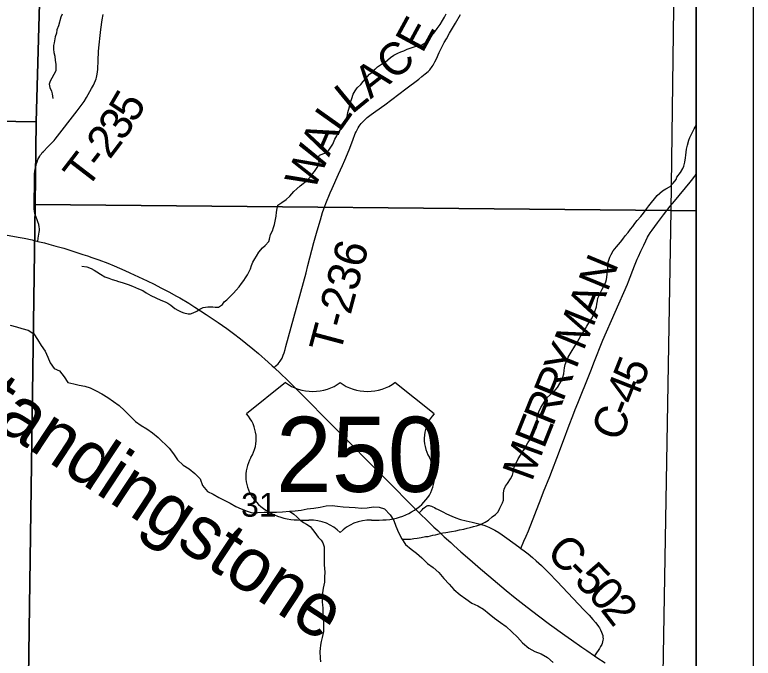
# Model space of a CAD drawing. Extents: x 0 to 34, y 0 to 22.
# Drawn here: x 24.203 to 25.5, y 14.665 to 15.795 of the extents above; entities that cross this region are included whole.
import ezdxf

# ---------------------------------------------------------------- set-up
doc = ezdxf.new("R2010")
doc.units = 0
for name, color, linetype in [('GM_X_Corporation', 7, 'Continuous'), ('GM_X_County_Road', 7, 'Continuous'), ('GM_X_County_Road_Text', 7, 'Continuous'), ('GM_X_Major_River', 7, 'Continuous'), ('GM_X_Major_River_Text', 7, 'Continuous'), ('GM_X_Minor_River', 7, 'Continuous'), ('GM_X_Section_Text', 7, 'Continuous'), ('GM_X_Township_Road', 7, 'Continuous'), ('GM_X_Township_Road_Text', 7, 'Continuous'), ('GM_X_US_Location', 7, 'Continuous'), ('GM_X_US_Route', 7, 'Continuous'), ('GM_X_US_Shield', 7, 'Continuous'), ('SH_Data', 7, 'Continuous')]:
    doc.layers.add(name, color=color, linetype=linetype)

msp = doc.modelspace()

# ---------------------------------------------------------------- linework, layer by layer
at = {"layer": 'GM_X_Corporation'}
msp.add_lwpolyline([(20.2208, 16.9558), (20.1987, 15.2691), (20.203, 14.81), (20.2016, 14.6512), (20.2571, 14.6508), (21.1282, 14.6279), (21.314, 14.623), (22.3464, 14.612), (22.9003, 14.6033), (24.2301, 14.5912), (24.2265, 14.4444), (24.4406, 14.442), (25.338, 14.4317), (25.4, 14.4307), (25.4, 19.0068)], dxfattribs=at)
for points in [[(23.2579, 16.628), (23.7676, 16.6453), (24.2698, 16.6327), (24.2658, 16.4792), (24.2407, 15.6067), (23.2418, 15.623)], [(24.2658, 16.4792), (25.3688, 16.474), (25.3552, 15.4512), (24.2392, 15.4615), (24.2407, 15.6067)], [(25.4, 15.4506), (25.4, 16.4736), (25.3688, 16.474), (25.3552, 15.4512)], [(23.2418, 15.623), (24.2407, 15.6067), (24.2392, 15.4615), (24.2269, 14.5903), (23.2254, 14.5998)], [(24.2392, 15.4615), (25.3552, 15.4512), (25.338, 14.4337), (25.2167, 14.4344), (24.2243, 14.4432), (24.2269, 14.5903)], [(25.4, 14.4329), (25.4, 15.4506), (25.3552, 15.4512), (25.338, 14.4337)]]:
    msp.add_lwpolyline(points, close=True, dxfattribs=at)
at = {"layer": 'GM_X_County_Road'}
for points in [[(25.0917, 14.8577), (25.0975, 14.8702), (25.1016, 14.8794), (25.1053, 14.8884), (25.1275, 14.9457), (25.132, 14.9569), (25.143, 14.984), (25.1478, 14.9961), (25.1553, 15.016), (25.1667, 15.0474), (25.177, 15.0744), (25.1833, 15.0908), (25.1876, 15.1016), (25.1921, 15.1125), (25.2127, 15.1635), (25.215, 15.1696), (25.2212, 15.1867), (25.2257, 15.1982), (25.23, 15.2088), (25.2362, 15.2234), (25.279, 15.3218), (25.2808, 15.3262), (25.2918, 15.3538), (25.2965, 15.3656), (25.2985, 15.3701), (25.3028, 15.3794), (25.3077, 15.3903), (25.3114, 15.3979), (25.3145, 15.404), (25.3161, 15.4069), (25.3193, 15.412), (25.3224, 15.4166), (25.3319, 15.4296), (25.3427, 15.4437), (25.3542, 15.4585), (25.3616, 15.4676), (25.3895, 15.5008), (25.3917, 15.5038), (25.3972, 15.5115), (25.4, 15.5159)], [(24.9136, 14.92), (24.916, 14.9227), (24.9185, 14.9255), (24.9207, 14.9277), (24.9226, 14.9294), (24.9244, 14.9309), (24.9254, 14.9316), (24.9269, 14.9324), (24.9286, 14.9329), (24.9309, 14.933), (24.9326, 14.9326), (24.9351, 14.9317), (24.9373, 14.9307), (24.9401, 14.9293), (24.9429, 14.9278), (24.9467, 14.9259)], [(24.9467, 14.9259), (24.955, 14.9217), (24.9615, 14.9185), (24.9709, 14.9141), (24.975, 14.9124), (24.9794, 14.9106), (24.9824, 14.9095), (24.9858, 14.9085), (24.9962, 14.906), (25.0063, 14.9039), (25.0134, 14.9023), (25.0204, 14.9004), (25.0268, 14.8984), (25.0318, 14.8966), (25.0368, 14.8946), (25.0418, 14.8922), (25.0463, 14.8897), (25.0533, 14.8854), (25.0591, 14.8815), (25.0673, 14.8757), (25.0882, 14.8604), (25.0917, 14.8577), (25.0978, 14.8533), (25.1046, 14.848), (25.1127, 14.8418), (25.119, 14.8362), (25.1281, 14.8278), (25.1361, 14.8199), (25.1409, 14.8151), (25.1558, 14.7996), (25.2026, 14.7501), (25.212, 14.7404), (25.2186, 14.7327), (25.2232, 14.7274), (25.2271, 14.7222), (25.2281, 14.7208)], [(25.2281, 14.7208), (25.23, 14.718), (25.2318, 14.7148), (25.2338, 14.7108), (25.235, 14.7076), (25.2358, 14.7046), (25.2362, 14.7018), (25.2363, 14.699), (25.2361, 14.6967), (25.2356, 14.6939), (25.2348, 14.691), (25.2339, 14.6888), (25.2321, 14.6854), (25.2302, 14.6821), (25.2278, 14.6785), (25.2249, 14.6745), (25.2211, 14.6691)]]:
    msp.add_lwpolyline(points, dxfattribs=at)
at = {"layer": 'GM_X_Major_River'}
for points in [[(24.1955, 15.2495), (24.2062, 15.2466), (24.2161, 15.244), (24.2267, 15.241), (24.237, 15.2347), (24.2431, 15.2245), (24.25, 15.2139), (24.2566, 15.2041), (24.2612, 15.1935), (24.2654, 15.1836), (24.2727, 15.1738), (24.2822, 15.1697), (24.2903, 15.1592), (24.2968, 15.149), (24.3071, 15.1468), (24.3166, 15.1446), (24.3264, 15.1428), (24.3359, 15.1394), (24.3466, 15.1346), (24.3565, 15.1294), (24.3668, 15.1226), (24.3767, 15.1159), (24.3866, 15.1087), (24.3961, 15.1001), (24.4053, 15.0903), (24.4156, 15.0805), (24.4255, 15.0734), (24.4351, 15.0678), (24.4454, 15.0606), (24.4553, 15.0527), (24.4748, 15.0335), (24.4824, 15.0237), (24.4889, 15.0135), (24.4993, 15.0038), (24.5099, 14.9974), (24.5195, 14.9895), (24.529, 14.9801), (24.5333, 14.968), (24.5421, 14.9578), (24.552, 14.9529), (24.5619, 14.947), (24.5722, 14.9417), (24.5817, 14.9369), (24.5916, 14.9316), (24.6011, 14.9272), (24.6112, 14.9229)], [(24.6112, 14.9229), (24.6205, 14.9201), (24.6303, 14.9206), (24.6413, 14.9214), (24.6527, 14.9215), (24.6629, 14.9212), (24.6735, 14.9217), (24.6857, 14.9233), (24.6955, 14.9238), (24.7061, 14.9247), (24.7167, 14.927)], [(24.7167, 14.927), (24.7288, 14.9286), (24.7398, 14.9299), (24.7504, 14.9322), (24.7606, 14.9331), (24.7701, 14.932), (24.7803, 14.931), (24.7906, 14.9303), (24.8012, 14.9293), (24.8122, 14.9286), (24.8224, 14.9291), (24.833, 14.9307), (24.8433, 14.93), (24.8528, 14.9274), (24.8627, 14.9169), (24.8689, 14.9067), (24.8727, 14.8965), (24.8774, 14.8855), (24.8828, 14.8745), (24.8897, 14.8647), (24.8992, 14.8565), (24.9088, 14.8493), (24.9183, 14.8411), (24.9282, 14.8313), (24.9382, 14.8241), (24.9477, 14.8155), (24.9565, 14.8049), (24.9661, 14.7952), (24.9745, 14.7854), (24.9852, 14.776), (24.9955, 14.7692), (25.0058, 14.7617), (25.0164, 14.7569), (25.0263, 14.7513), (25.0363, 14.7426), (25.0458, 14.7355), (25.0561, 14.7276), (25.0664, 14.7205), (25.0763, 14.7115), (25.0859, 14.7017), (25.0947, 14.6919), (25.1058, 14.6825), (25.1164, 14.6769), (25.1274, 14.6724), (25.1385, 14.6664), (25.1488, 14.6574)]]:
    msp.add_lwpolyline(points, dxfattribs=at)
at = {"layer": 'GM_X_Minor_River'}
for points in [[(24.2864, 15.7961), (24.2841, 15.7908), (24.28, 15.7756), (24.277, 15.7683), (24.2766, 15.7626), (24.2744, 15.7558), (24.2725, 15.7455), (24.2717, 15.7406), (24.2714, 15.7341), (24.2718, 15.7284), (24.2737, 15.722), (24.2745, 15.7143), (24.2753, 15.7083), (24.2756, 15.7029), (24.2753, 15.6961), (24.2719, 15.69), (24.2685, 15.6832), (24.2658, 15.6782), (24.264, 15.6729), (24.2647, 15.6668), (24.2678, 15.6607), (24.2689, 15.6558), (24.27, 15.6476)], [(24.771, 15.5871), (24.7759, 15.5936), (24.7801, 15.5993), (24.7831, 15.6058), (24.785, 15.6103), (24.7869, 15.6164), (24.7884, 15.6233), (24.791, 15.6332), (24.7929, 15.6411), (24.7951, 15.6476), (24.7978, 15.6556), (24.8012, 15.6613), (24.8046, 15.6666), (24.811, 15.6723), (24.8152, 15.6773), (24.819, 15.6822), (24.8265, 15.6902), (24.8322, 15.6948), (24.836, 15.6994), (24.8405, 15.7032), (24.8474, 15.7078), (24.8538, 15.7116), (24.8587, 15.7158), (24.8633, 15.7196), (24.869, 15.7238), (24.8762, 15.7276), (24.8815, 15.7299), (24.8864, 15.7314), (24.8925, 15.7341), (24.8978, 15.736), (24.9065, 15.739), (24.9114, 15.7402), (24.9167, 15.7413), (24.9221, 15.7444), (24.9277, 15.7486), (24.9319, 15.7531), (24.9357, 15.7585), (24.941, 15.7649), (24.9451, 15.7707), (24.9501, 15.7779), (24.9546, 15.7844), (24.958, 15.7904), (24.9606, 15.7965)], [(25.2481, 15.3694), (25.2503, 15.3739), (25.2541, 15.38), (25.2602, 15.3873), (25.267, 15.3952), (25.2708, 15.4006), (25.2753, 15.4063), (25.2802, 15.4124), (25.2844, 15.4181), (25.2885, 15.423), (25.2923, 15.4284), (25.2965, 15.4337), (25.3025, 15.4405), (25.3075, 15.4466), (25.3131, 15.4543), (25.3169, 15.4592), (25.3215, 15.4649), (25.3264, 15.4714), (25.3313, 15.4775), (25.3358, 15.4813), (25.3408, 15.4855), (25.3468, 15.4893), (25.354, 15.4935), (25.3597, 15.4992), (25.3646, 15.5053), (25.3661, 15.5098), (25.3722, 15.5175), (25.3763, 15.5247), (25.3782, 15.5292), (25.3797, 15.5357), (25.3812, 15.5437), (25.3816, 15.5483), (25.3823, 15.5536), (25.3831, 15.5589), (25.3846, 15.5658), (25.3872, 15.5745), (25.3887, 15.5794), (25.3929, 15.5874), (25.3963, 15.5947), (25.3997, 15.6004), (25.4, 15.6011)], [(24.3212, 15.3532), (24.3301, 15.3521), (24.3373, 15.3491), (24.3426, 15.3464), (24.3476, 15.3434), (24.3537, 15.3392), (24.3613, 15.3347), (24.3685, 15.332), (24.3742, 15.3298), (24.3807, 15.3279), (24.3856, 15.3264), (24.3917, 15.3248), (24.4023, 15.3211), (24.4099, 15.318), (24.4206, 15.3135), (24.4282, 15.3105), (24.4339, 15.3067), (24.4422, 15.3021), (24.451, 15.2976), (24.4601, 15.2934), (24.4677, 15.2904), (24.4723, 15.2885), (24.4772, 15.2851), (24.4844, 15.279), (24.4898, 15.276), (24.4958, 15.2733), (24.5004, 15.2711), (24.5076, 15.2696), (24.5122, 15.2699), (24.5167, 15.2715), (24.5228, 15.2745), (24.5281, 15.2776), (24.5345, 15.2806), (24.5425, 15.2822), (24.5509, 15.2822), (24.5554, 15.2814), (24.5611, 15.2814), (24.5679, 15.286), (24.571, 15.2906), (24.5759, 15.294), (24.5804, 15.299), (24.5873, 15.3058), (24.5922, 15.3112), (24.5975, 15.3169), (24.6016, 15.3226), (24.6054, 15.3279), (24.6088, 15.3329), (24.6122, 15.3382), (24.6149, 15.3439), (24.6171, 15.3488), (24.619, 15.3542), (24.6217, 15.3603), (24.6251, 15.3663), (24.6277, 15.3709), (24.6319, 15.3778), (24.6383, 15.3854), (24.6432, 15.3899), (24.6493, 15.3964), (24.6508, 15.401), (24.6523, 15.409), (24.6557, 15.4154), (24.6576, 15.4215), (24.6594, 15.4265), (24.6606, 15.4326), (24.6621, 15.4413), (24.6632, 15.4482), (24.6639, 15.4546), (24.6654, 15.4603), (24.6722, 15.4653), (24.6802, 15.4702), (24.6866, 15.476), (24.6935, 15.4843), (24.6984, 15.4889), (24.7048, 15.4942), (24.7097, 15.4984), (24.7158, 15.5034), (24.7219, 15.5098), (24.7264, 15.5152), (24.7298, 15.5197), (24.7332, 15.5251), (24.7374, 15.5312), (24.7377, 15.5361), (24.7358, 15.5422), (24.7385, 15.5483), (24.746, 15.5513), (24.7506, 15.5529), (24.7551, 15.5571), (24.7582, 15.5624), (24.7616, 15.5677), (24.7653, 15.5765), (24.7687, 15.5822), (24.771, 15.5871)], [(25.1521, 15.1358), (25.1561, 15.14), (25.1602, 15.1472), (25.1636, 15.1518), (25.1655, 15.1582), (25.1674, 15.1643), (25.1681, 15.1704), (25.1689, 15.175), (25.17, 15.1807), (25.1719, 15.1864), (25.1753, 15.1936), (25.1806, 15.2024), (25.1866, 15.213), (25.19, 15.2183), (25.1942, 15.2256), (25.1979, 15.2321), (25.2029, 15.2397), (25.2078, 15.2477), (25.2127, 15.2553), (25.2161, 15.261), (25.2187, 15.2659), (25.2218, 15.2735), (25.2248, 15.2819), (25.2255, 15.2865), (25.2263, 15.2922), (25.227, 15.2971), (25.2293, 15.3021), (25.2327, 15.3085), (25.2349, 15.3131), (25.2376, 15.318), (25.241, 15.3256), (25.2425, 15.3302), (25.2436, 15.3386), (25.244, 15.3443), (25.2447, 15.3504), (25.2451, 15.3557), (25.2454, 15.3602), (25.2481, 15.3694)], [(24.8828, 14.8745), (24.8842, 14.8738), (24.8914, 14.8742), (24.8983, 14.8742), (24.9043, 14.875), (24.91, 14.8757), (24.9172, 14.8769), (24.9244, 14.8784), (24.929, 14.8788), (24.9374, 14.8807), (24.9419, 14.8815), (24.9502, 14.8838), (24.9548, 14.8849), (24.9605, 14.8857), (24.97, 14.8873), (24.978, 14.8888), (24.9844, 14.8903), (24.992, 14.8915), (24.9977, 14.893), (25.003, 14.8945), (25.0087, 14.8961), (25.014, 14.8972), (25.0212, 14.8995), (25.0295, 14.9037), (25.0352, 14.9075), (25.0417, 14.9132), (25.0474, 14.9174), (25.0519, 14.922), (25.0549, 14.9281), (25.0576, 14.933), (25.0598, 14.9376), (25.0613, 14.9425), (25.0617, 14.9482), (25.0617, 14.9551), (25.0628, 14.9619), (25.0651, 14.9672), (25.0685, 14.9718), (25.0741, 14.9798), (25.0771, 14.9863), (25.0783, 14.9912), (25.0805, 15.0003), (25.0839, 15.0076), (25.0873, 15.0152), (25.0911, 15.0213), (25.0937, 15.0258), (25.0987, 15.0334), (25.1013, 15.038), (25.1043, 15.0433), (25.1081, 15.049), (25.1115, 15.054), (25.1141, 15.0586), (25.1164, 15.0639), (25.1191, 15.0688), (25.1209, 15.0745), (25.1217, 15.0795), (25.1209, 15.0852), (25.1213, 15.0924), (25.1235, 15.0974), (25.1273, 15.105), (25.1341, 15.116), (25.1371, 15.1213), (25.1521, 15.1358)], [(24.6857, 14.9233), (24.6935, 14.9179), (24.6984, 14.913), (24.7034, 14.9084), (24.7102, 14.9035), (24.7156, 14.9001), (24.722, 14.8963), (24.73, 14.8857), (24.7361, 14.8777), (24.7415, 14.8724), (24.7445, 14.8678), (24.7468, 14.8602), (24.7468, 14.8526), (24.7469, 14.845), (24.7465, 14.8359), (24.7469, 14.8287), (24.7473, 14.8222), (24.7477, 14.8161), (24.747, 14.807), (24.747, 14.7986), (24.7459, 14.7929), (24.7451, 14.788), (24.744, 14.78), (24.7436, 14.7755), (24.7433, 14.7698), (24.7433, 14.7633), (24.7437, 14.7584), (24.7445, 14.7527), (24.7445, 14.7435), (24.7445, 14.7352), (24.7453, 14.7283), (24.7457, 14.7223), (24.7453, 14.7166), (24.7454, 14.712), (24.7442, 14.7063), (24.7431, 14.7013), (24.7416, 14.6945), (24.7405, 14.688), (24.7394, 14.682), (24.739, 14.6766), (24.7398, 14.6652), (24.7402, 14.6584)]]:
    msp.add_lwpolyline(points, dxfattribs=at)
at = {"layer": 'GM_X_Township_Road'}
for points in [[(24.2613, 15.5626), (24.2684, 15.5698), (24.2724, 15.5742), (24.2741, 15.5763), (24.3131, 15.6262), (24.3185, 15.6329), (24.3251, 15.6425), (24.3293, 15.6493), (24.3382, 15.6651), (24.3415, 15.6712), (24.3452, 15.6795), (24.3463, 15.6821), (24.3471, 15.6844), (24.3477, 15.6875), (24.3487, 15.6937), (24.3492, 15.699), (24.3499, 15.7142), (24.3506, 15.7303), (24.3511, 15.7368), (24.3538, 15.7637), (24.3545, 15.769), (24.357, 15.7861), (24.3585, 15.795)], [(24.6586, 15.1754), (24.6616, 15.1781), (24.6656, 15.1819), (24.6677, 15.1841), (24.6694, 15.1863), (24.6708, 15.1885), (24.6728, 15.1919), (24.6749, 15.1968), (24.6763, 15.2011), (24.6782, 15.2069), (24.6796, 15.2123), (24.6841, 15.2292), (24.7148, 15.3417), (24.718, 15.3542), (24.7285, 15.3946), (24.731, 15.4033), (24.7333, 15.4114), (24.7362, 15.4214), (24.74, 15.4346), (24.7418, 15.4409), (24.7439, 15.4476), (24.7478, 15.4586), (24.7497, 15.4636), (24.7572, 15.482), (24.7606, 15.4899), (24.7719, 15.5146), (24.7789, 15.5298), (24.7831, 15.5394), (24.7905, 15.5578), (24.7969, 15.5747), (24.8013, 15.5861), (24.8028, 15.5893), (24.8065, 15.5963), (24.8081, 15.5989), (24.8098, 15.6012), (24.8119, 15.6038), (24.8153, 15.6074), (24.8186, 15.6108), (24.8223, 15.6141), (24.8291, 15.6194), (24.8372, 15.6254), (24.8529, 15.6368), (24.8903, 15.6648), (24.9128, 15.6816), (24.9184, 15.6861), (24.924, 15.6908), (24.929, 15.6954), (24.9319, 15.6983), (24.9333, 15.6999), (24.9352, 15.7022), (24.9365, 15.7042), (24.9378, 15.7065), (24.941, 15.7123), (24.9437, 15.7175), (24.9487, 15.7286), (24.9519, 15.7356), (24.9549, 15.7414), (24.9573, 15.7458), (24.9612, 15.7527), (24.9668, 15.7623), (24.9771, 15.7799), (24.9863, 15.7953)], [(24.244, 15.3969), (24.2447, 15.4023), (24.2463, 15.4128), (24.2466, 15.416), (24.2467, 15.419), (24.2464, 15.4223), (24.2457, 15.4265), (24.2439, 15.4314), (24.2427, 15.4347), (24.2392, 15.444), (24.2389, 15.4454), (24.238, 15.45), (24.2376, 15.4542), (24.2373, 15.4578), (24.2375, 15.4709), (24.2378, 15.4944), (24.2379, 15.5116), (24.238, 15.5154), (24.2385, 15.5201), (24.239, 15.5228), (24.2407, 15.5307), (24.2415, 15.5334), (24.2426, 15.5366), (24.2442, 15.5404), (24.2455, 15.5437), (24.2473, 15.5467), (24.2486, 15.5486), (24.2501, 15.5507), (24.2518, 15.5529), (24.2536, 15.5547), (24.2613, 15.5626)]]:
    msp.add_lwpolyline(points, dxfattribs=at)
at = {"layer": 'GM_X_US_Route'}
for points in [[(24.187, 15.4085), (24.2093, 15.4044), (24.22, 15.4023), (24.2341, 15.3993), (24.244, 15.3969), (24.2555, 15.394), (24.2632, 15.392)], [(24.2632, 15.392), (24.2756, 15.3887), (24.2893, 15.3848), (24.3018, 15.381), (24.3231, 15.374), (24.3314, 15.3712)], [(24.3314, 15.3712), (24.3388, 15.3686), (24.3512, 15.3643), (24.3666, 15.3585), (24.3778, 15.3539), (24.3964, 15.3459), (24.4052, 15.3419), (24.4359, 15.3276), (24.4484, 15.3216), (24.4599, 15.3155), (24.4737, 15.3083), (24.4876, 15.3008), (24.493, 15.2977), (24.5092, 15.2881), (24.5196, 15.2816), (24.5395, 15.2687), (24.5485, 15.2627), (24.5606, 15.2545), (24.5757, 15.2438), (24.5872, 15.2353), (24.5998, 15.2255), (24.6093, 15.218), (24.6216, 15.208), (24.6311, 15.1999), (24.6486, 15.1845), (24.6552, 15.1785), (24.6586, 15.1754), (24.6704, 15.1644), (24.6816, 15.1537), (24.6998, 15.1356), (24.7671, 15.0678), (24.8506, 14.9835), (24.8783, 14.9557), (24.8838, 14.9501), (24.9089, 14.9249), (24.9136, 14.92), (24.9291, 14.905), (24.9394, 14.8949), (24.946, 14.8889), (24.9576, 14.8781), (24.969, 14.8679), (24.9745, 14.8626), (24.9869, 14.8515), (25.0022, 14.838), (25.0212, 14.8217), (25.0355, 14.8097), (25.066, 14.7839), (25.0821, 14.7709), (25.1029, 14.7546), (25.1227, 14.7394), (25.1424, 14.7249), (25.1694, 14.7053), (25.1808, 14.6974), (25.199, 14.6845), (25.2079, 14.6785), (25.2211, 14.6691), (25.2255, 14.6662), (25.24, 14.6567)]]:
    msp.add_lwpolyline(points, dxfattribs=at)
at = {"layer": 'GM_X_US_Shield'}
for p, q in [((24.6787, 15.1492), (24.61, 15.0943)), ((24.9396, 15.0943), (24.8709, 15.1492)), ((24.7061, 14.9075), (24.7199, 14.9075)), ((24.8297, 14.9075), (24.8435, 14.9075))]:
    msp.add_line(p, q, dxfattribs=at)
for centre, major_axis, start_param, end_param in [((24.7267, 15.1884), (-0.0687, 0), 0.795399, 2.346194), ((24.8229, 15.1884), (-0.0687, 0), 0.795399, 2.346194), ((24.5313, 15.0502), (0.0961, 0), 5.838949, 6.894067), ((25.0183, 15.0502), (-0.0961, 0), 5.672304, 6.727422), ((24.7051, 14.9844), (0.0961, 0), 2.702327, 4.723529), ((24.8445, 14.9844), (-0.0961, 0), 1.559657, 3.580859), ((24.7199, 14.8526), (-0.0687, 0), 3.785094, 4.712389), ((24.8297, 14.8526), (-0.0687, 0), 4.712389, 5.639684)]:
    msp.add_ellipse(centre, major_axis=major_axis, ratio=0.8, start_param=start_param, end_param=end_param, dxfattribs=at)
at = {"layer": 'SH_Data'}
for points in [[(18.5, 20.5), (25.5, 20.5), (25.5, 13.5), (18.5, 13.5)], [(18.6, 20.4), (25.4, 20.4), (25.4, 13.6), (18.6, 13.6)]]:
    msp.add_lwpolyline(points, close=True, dxfattribs=at)

# ---------------------------------------------------------------- texts
at = {"layer": 'GM_X_County_Road_Text'}
for s, rotation, p in [('N', 67.516, (25.2438, 15.3066)), ('A', 67.9456, (25.225, 15.2604)), ('M', 67.9479, (25.2019, 15.2032)), ('Y', 67.9501, (25.1831, 15.1569)), ('5', 68.3096, (25.3047, 15.14)), ('R', 67.9491, (25.1656, 15.1136)), ('4', 68.4698, (25.292, 15.1077)), ('R', 67.9464, (25.1481, 15.0704)), ('C', 68.5425, (25.2666, 15.0431)), ('-', 68.5226, (25.2835, 15.0862)), ('E', 68.1492, (25.1323, 15.031)), ('M', 70.0368, (25.1114, 14.9735)), ('C', 316.2574, (25.1343, 14.8474)), ('5', 314.2314, (25.1837, 14.7994)), ('-', 314.8002, (25.1675, 14.8157)), ('0', 312.8165, (25.2076, 14.7748)), ('2', 307.8537, (25.2304, 14.7503))]:
    msp.add_text(s, height=0.0568, rotation=rotation, dxfattribs=at).set_placement(p)
at = {"layer": 'GM_X_Major_River_Text'}
msp.add_text('Standingstone', height=0.094695, rotation=326.5804, dxfattribs=at).set_placement((24.0668, 15.138))
at = {"layer": 'GM_X_Section_Text'}
msp.add_text('31', height=0.04186, rotation=0, dxfattribs=at).set_placement((24.6008, 14.9134))
at = {"layer": 'GM_X_Township_Road_Text'}
for s, height, rotation, p in [('E', 0.0568, 61.4503, (24.9191, 15.7255)), ('C', 0.0568, 39.506, (24.868, 15.6776)), ('A', 0.0568, 38.4431, (24.828, 15.6458)), ('L', 0.0568, 39.3452, (24.7953, 15.619)), ('5', 0.0568, 59.6409, (24.4145, 15.6028)), ('3', 0.0568, 56.7957, (24.3937, 15.5709)), ('L', 0.0568, 54.698, (24.7735, 15.5873)), ('2', 0.0568, 52.7459, (24.37, 15.5394)), ('A', 0.0568, 66.6079, (24.7552, 15.5441)), ('W', 0.0568, 65.8521, (24.7279, 15.4833)), ('T', 0.0568, 52.4881, (24.3295, 15.4869)), ('-', 0.0568, 52.2277, (24.3554, 15.5205)), ('T-236', 0.05682, 75.0733, (24.7745, 15.1973))]:
    msp.add_text(s, height=height, rotation=rotation, dxfattribs=at).set_placement(p)
at = {"layer": 'GM_X_US_Location'}
for s in ['0', '/']:
    msp.add_text(s, height=0.000189, dxfattribs=at).set_placement((24.7749, 15.0228))
msp.add_text('250', height=0.000189, rotation=0, dxfattribs=at).set_placement((24.7166, 14.9836))
at = {"layer": 'GM_X_US_Shield'}
msp.add_text('250', height=0.13184, dxfattribs=at).set_placement((24.662, 14.957))

doc.saveas('drawing.dxf')
